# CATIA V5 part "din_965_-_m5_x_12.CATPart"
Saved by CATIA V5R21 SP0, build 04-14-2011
Part number: din_965_-_m5_x_12
Definition: Countersunk Machine Screw according to DIN 965, DIN 965 - M5 x 12
Description: Countersunk Machine Screw according to DIN 965, DIN 965 - M5 x 12
Property "REFERENCE": "DIN 965 - d M5 x L 12"
Property "REFERENCE": "DIN 965 - d M5 x L 12"
Property "STANDARD": "DIN 965"
Property "STANDARD": "DIN 965"
Property "DESIGN": "Countersunk Machine Screw according to DIN 965, DIN 965 - M5 x 12"
Property "DESIGN": "Countersunk Machine Screw according to DIN 965, DIN 965 - M5 x 12"
Property "OMNICLASS23": "23.13.23.11.13.19"
Property "OMNICLASS23": "23.13.23.11.13.19"
Property "TraceParts.PartNumber": "32-22052013-115851"
Property "TraceParts.PartVersion": "1.2.4"
Property "TraceParts.InstanceId": "32-22052013-11585160B2WL6GTEX2CH80QP7KGZV39"
Property "TraceParts.PartStandardAcronym": "DIN"
Property "TraceParts.PartTitle": "Countersunk Machine Screw according to DIN 965"
Property "TRACEPARTS": "TRACEPARTS"
Property "TraceParts.PartLanguage": "en"
Publications: "Face", "Axis"
Bounding box of the stored display mesh (mm): x 0 to 12, y -4.599 to 4.599, z -4.599 to 4.599
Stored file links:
  C:\Users\zerma\Pictures\Stage Stomate\din_965_-_m5_x_12.CATPart
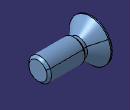
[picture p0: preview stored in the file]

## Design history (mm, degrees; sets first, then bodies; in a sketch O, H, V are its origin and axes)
AxisSystem1: origin (0, 0, 0), X (1, 0, 0), Y (0, 1, 0), Z (0, 0, 1)
Body1 "din_965_-_m5_x_12" (main body)
  Solid1: solid without history
  Thread1: diameter 5, depth 7.9, pitch 0.8, on face of Solid1, from face of Solid1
